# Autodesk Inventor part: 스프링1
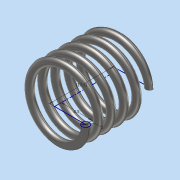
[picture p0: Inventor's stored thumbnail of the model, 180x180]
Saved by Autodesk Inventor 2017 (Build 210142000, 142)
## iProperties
Part Number: 스프링1
Material: 스테인레스 스틸
Document SubType Name: Modeling
Designer: MRC
Density: 8 g/cm^3
Appearance: 반연마
Mass: 6.54895 g
Surface Area: 16.6959 cm^2
Volume: 0.818619 cm^3
Author: MRC
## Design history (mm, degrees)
sketch "스케치1"
  geometry: L1 (0, 0)-(0, 17.5); L2 (0, 0)-(8.5, 0); L3 (0, 17.5)-(8.5, 17.5); C1 r 1 at (8.5, 0)
  constraints: 6 end point, 2 horizontal, 1 centre point, 1 coincident, 1 vertical
  dimensions: "d0" = 17.5 distance of L1.start L1.end (derived); "d1" = 8.5 distance of L1.start L2.end; "d2" = 2 diameter of C1
feature "코일1" pitch "d3" = 10; turns "d5" = 5; dims "d4" = 17.5 (= d0), "d6" = 0, angle "d7" = 90 deg, angle "d8" = 90 deg, "d9" = 0, "d10" = 0
sketch "스케치2"
  geometry: L1 (17.5, 13.489)-(0, 13.489); L2 (0, 13.489)-(0, -13.489); L3 (0, -13.489)-(17.5, -13.489); L4 (17.5, -13.489)-(17.5, 13.489); 2 further points
  constraints: 8 end point, 2 parallel, 1 coincident, 1 horizontal, 1 midpoint, 1 perpendicular
  dimensions: "d11" = 17.5 distance of L2.end L3.end (= d0)
extrude "돌출1" sketch "스케치2" stored distance "d12" = 0; taper "d13" = 0 deg
node "솔리드1"
